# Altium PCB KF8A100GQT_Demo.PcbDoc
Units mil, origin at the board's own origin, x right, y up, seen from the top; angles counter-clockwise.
Board outline 2167.2 x 3149.88 mil, 2 copper layers (Top Layer, Bottom Layer); 44 components, 80 nets, 251 pads, 32 vias.
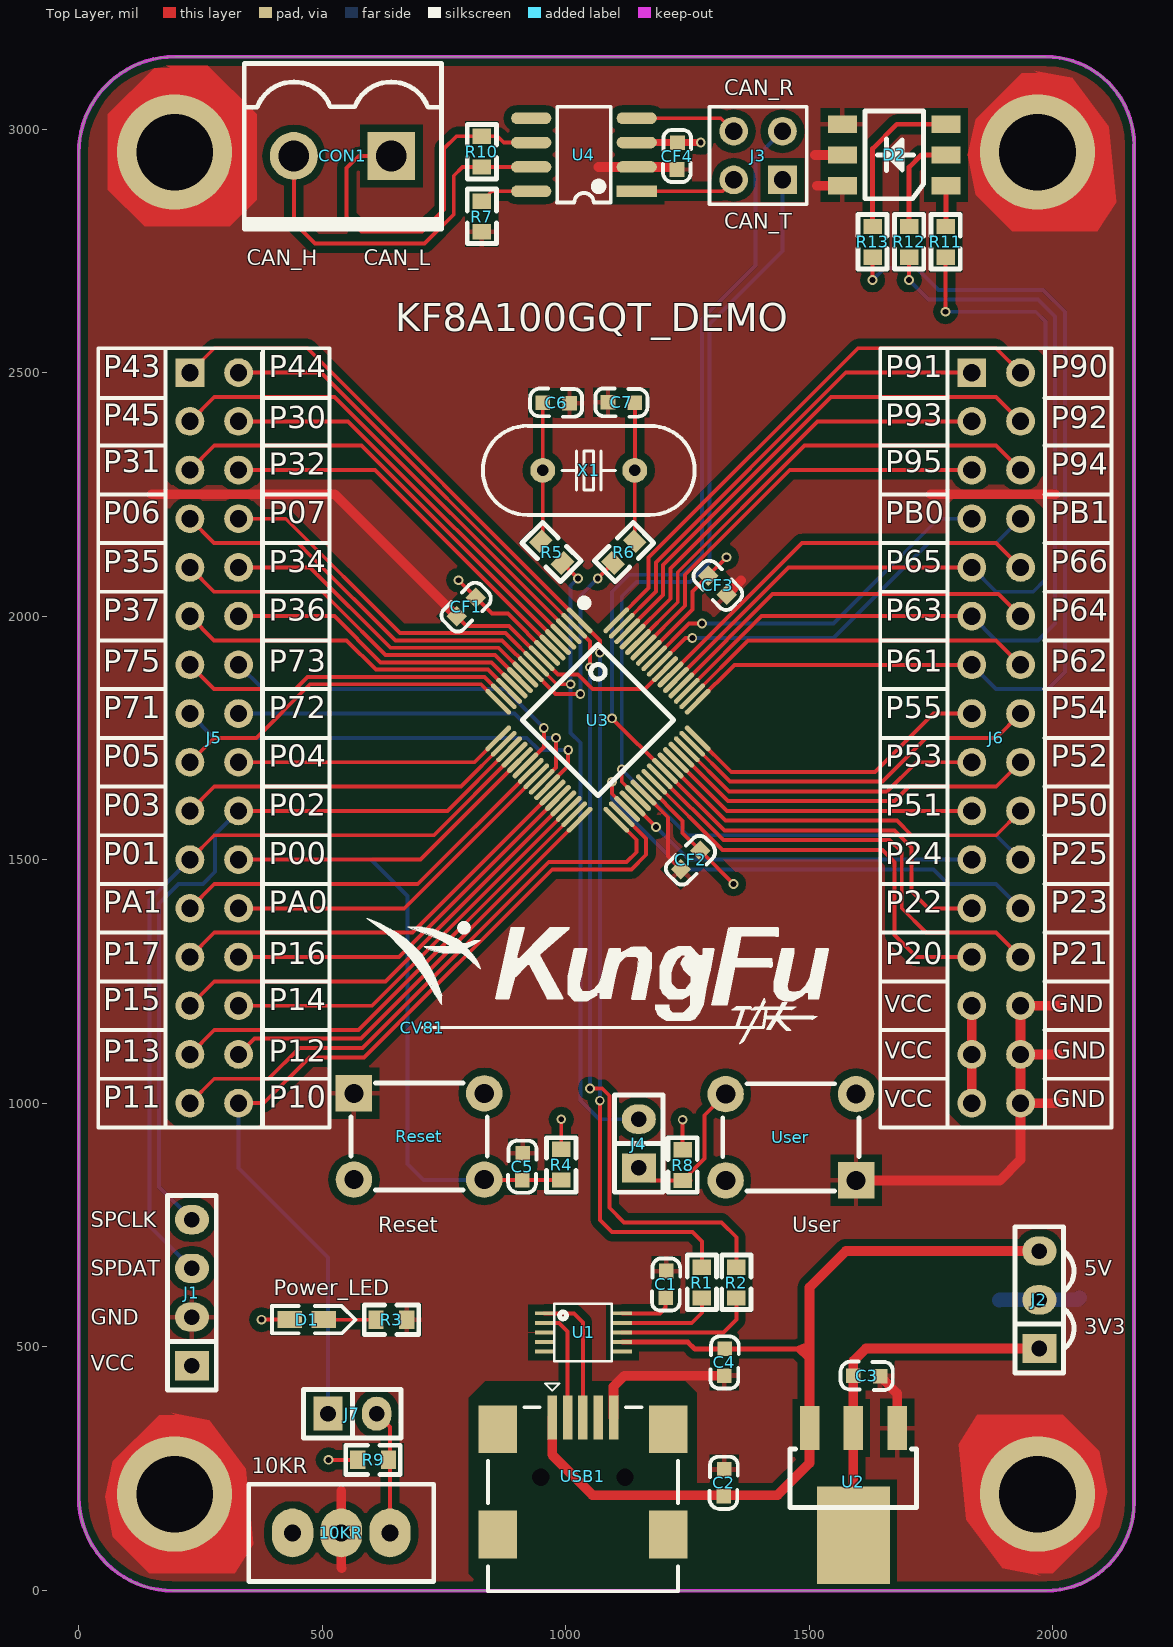
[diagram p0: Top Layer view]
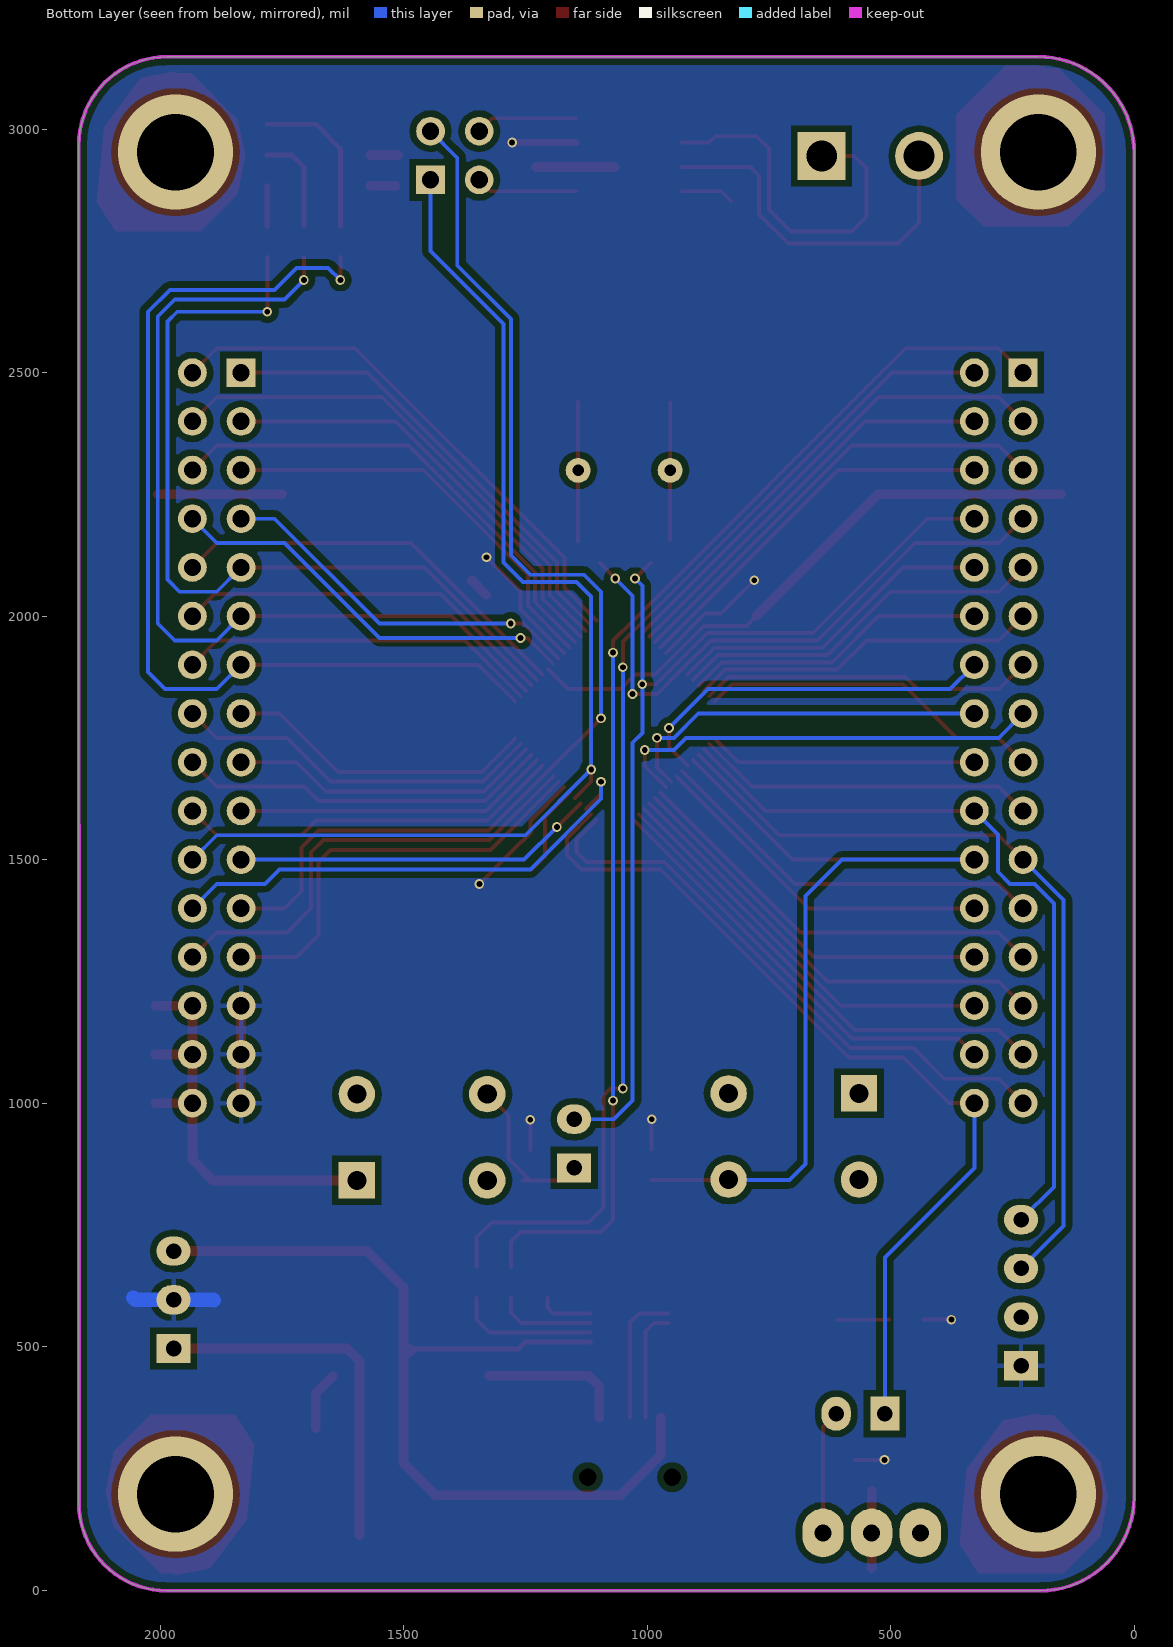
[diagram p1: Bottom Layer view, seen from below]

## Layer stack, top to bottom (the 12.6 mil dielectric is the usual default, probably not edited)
Top Layer: signal copper 1.4
Dielectric: dielectric 12.6, FR-4, Dk 4.8
Bottom Layer: signal copper 1.4

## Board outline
193.16,-1.33 cw(c193.16,191.83) 0,190 0,2951.69 cw(c196.85,2951.69) 196.85,3148.54 1985.93,3148.54 cw(c1985.93,2967.27) 2167.2,2967.27 2167.14,2967.27 2166.9,179.02 2166.97,179.02 cw(c1986.61,179.02) 1986.61,-1.33

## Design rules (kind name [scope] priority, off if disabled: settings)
Clearance [All] p1: gap=5
HoleSize [All] p1: absolutevalues=TRUE maxlimit=157.48 minlimit=1 maxpercent=80.000 minpercent=20.000
PolygonConnect [All vs IsVia] p1: connectstyle=Direct reliefconductorwidth=10 reliefentries=4 polygonreliefangle="90 Angle"
RoutingVias [All] p1: holewidth=28 width=50 viastyle="Through Hole" minholewidth=12 minwidth=20 maxholewidth=157.48 maxwidth=236.22
SolderMaskExpansion [All] p1: expansion=4
TestPointUsage [All] p1: valid=0 allowmultiple=FALSE
Testpoint [All] p1: side=15 testpointundercomponent=TRUE minsize=40 maxsize=100 preferedsize=60 minholesize=0 maxholesize=40 preferedholesize=32 testpointgrid=1 style=1023 order=0-112345678
Width [All] p1: maxlimit=30 minlimit=8 preferedwidth=10
18 further rules are at their usual default settings.

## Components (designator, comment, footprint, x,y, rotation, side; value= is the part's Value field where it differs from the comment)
10KR "10K" 3296W 539.02,117.4 r0 top (schematic designator VR1)
C1 "0.1uF" 0603C 1204.72,599.92 r90 top
C2 "22uF" 0603C 1325.55,248.03 r270 top
C3 "10uF" 0603C 1645.67,438.82 r180 top
C4 "10nF" 0603C 1325,440 r90 top
C5 "100nF" 0603C 912.01,897.05 r270 top
C6 "22pF" 0603C 1007.87,2437.01 r180 top
C7 "22pF" 0603C 1086.61,2439.72 r0 top
CF1 "100nF" 0603C 775.59,2000 r45 top
CF2 "100nF" 0603C 1236.22,1480.32 r45 top
CF3 "100nF" 0603C 1330.71,2043.31 r135 top
CF4 "100nF" 0603C 1229.78,2972.32 r270 top
CON1 "Connector-2P" KF2EDG-5.08-2P 641.73,2944.88 r180 top
CV81 "Comment" LOGO 705,1155 r0 top
D1 "LED" LED-0603B 433.07,555.12 r0 top
D2 "LED-5050" LED-5050W 1779.53,2881.89 r180 top
J1 "DEBUG" "Pin HDR1X4/2.54mm-S" 232.28,460.63 r180 top
J2 "Pin HDR1X3" "Pin HDR1X3/2.54mm-S" 1972.44,496.06 r180 top
J3 "Pin HDR2X2" "Pin HDR2X2/2.54mm-S" 1444.88,2895.75 r90 top
J4 "Pin HDR1X2" "Pin HDR1X2/2.54mm-S" 1150,866.93 r180 top
J5 "Pin HDR2X16" "Pin HDR2X16/2.54mm-S" 228.19,2499.92 r270 top locked
J6 "Pin HDR2X16" "Pin HDR2X16/2.54mm-S" 1833.86,2499.92 r270 top locked
J7 "Pin HDR1X2" "Pin HDR1X2/2.54mm-S" 511.81,362.2 r90 top
R1 "300R" 0603R 1279.53,662.91 r270 top
R2 "300R" 0603R 1350.39,662.91 r270 top
R3 "470R" 0603R 673.23,555.12 r180 top
R4 "10K" 0603R 990.75,841.93 r90 top
R5 "0R" 0603R 948.82,2153.54 r315 top
R6 "0R" 0603R 1141.73,2153.54 r225 top
R7 "NC" 0603R 827.64,2851.97 r270 top
R8 "10K" 0603R 1240,903.93 r270 top
R9 "10K" 0603R 573.19,267.4 r0 top
R10 "120R" 0603R 827.64,2922.32 r90 top
R11 "300R" 0603R 1780,2800 r270 top
R12 "300R" 0603R 1705,2800 r270 top
R13 "300R" 0603R 1630,2800 r270 top
Reset "KEY" DIP-6X6X4.3 565,1020 r0 top (schematic designator K1)
U1 "CH340E" MSOP10 956.54,528.98 r0 top
U2 "AMS1117" SOT223 1590.55,332.52 r180 top
U3 "KF8A100GQT" "LQFP64 7x7" 1059.06,1779.53 r315 top locked
U4 "SN65HVD232D" SOP8 1145.67,2872.32 r180 top
USB1 "MINI-USB" USB-MINI-A 972.28,354.25 r0 top
User "KEY" DIP-6X6X4.3 1596.1,841.22 r180 top (schematic designator K2)
X1 "16M" "OSC HC-49S" 1047.24,2299.21 r180 top

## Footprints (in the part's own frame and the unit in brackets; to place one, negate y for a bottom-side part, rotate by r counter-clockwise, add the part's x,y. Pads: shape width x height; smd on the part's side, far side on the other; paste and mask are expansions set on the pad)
0603C [mil]
  rect 30x30 smd: 1(0.21,-0.35) 2(55.21,-1.35)
  silkscreen extent -26,-30 81,28, body extent -1,-15 62,17, height 12
0603R [mm]
  rect 0.8x0.965 smd: 1(0,0) 2(1.6,0)
  silkscreen extent -0.64,-0.76 2.21,0.76, body extent -0.04,-0.41 1.56,0.41, height 0.45
3296W [mil]
  oval 85x100 hole 35: 1(-100,0) 2(0,0) 3(100,0)
  silkscreen extent -190,-100 190,100, body extent -188,-94 188,94, height 455
DIP-6X6X4.3 [mm]
  rect 1.9x1.9 hole 1: 1(0,0)
  round 1.9 hole 1: 2(0,-4.5) 3(6.8,-4.5) 4(6.8,0)
  silkscreen extent -0.16,-5.04 6.96,0.54, body extent -0.66,-5.25 7.55,0.75, height 4.25
KF2EDG-5.08-2P [mm]
  rect 2.5x2.5 hole 1.6: 1(0,0)
  round 2.5 hole 1.6: 2(5.08,0)
  silkscreen extent -2.62,-4.83 7.67,3.81, body extent -2.54,-4.76 7.62,3.74, height 11.25
LED-0603B [mil]
  rect 50x35 smd: A(0,0.26) K(70,0.26)
  silkscreen extent -36,-28 135,28, body extent 4,-15 66,17, height 24
LED-5050W [mil]
  rect 59.06x35.43 smd: 1(-1.5,-2) 2(211.5,-2) 3(-1.5,-65) 4(211.5,-65) 5(-1.5,-128) 6(211.5,-128)
  silkscreen extent 45,-155 165,25, body extent -1,-162 211,35, height 65
LOGO [mil]
  silkscreen extent -114,-33 835,225
"LQFP64 7x7" [mm]
  oval 1.8x0.26 smd: 1(-4.352,3.254) 2(-4.352,2.854) 3(-4.352,2.454) 4(-4.352,2.054) 5(-4.352,1.654) 6(-4.352,1.254) 7(-4.352,0.854) 8(-4.352,0.454) 9(-4.352,0.054) 10(-4.352,-0.346) 11(-4.352,-0.746) 12(-4.352,-1.146) 13(-4.352,-1.546) 14(-4.352,-1.946) 15(-4.352,-2.346) 16(-4.352,-2.746) 33(4.352,-2.746) 34(4.352,-2.346) 35(4.352,-1.946) 36(4.352,-1.546) 37(4.352,-1.146) 38(4.352,-0.746) 39(4.352,-0.346) 40(4.352,0.054) 41(4.352,0.454) 42(4.352,0.854) 43(4.352,1.254) 44(4.352,1.654) 45(4.352,2.054) 46(4.352,2.454) 47(4.352,2.854) 48(4.352,3.254)
  oval 0.26x1.8 smd: 17(-3,-4.098) 18(-2.6,-4.098) 19(-2.2,-4.098) 20(-1.8,-4.098) 21(-1.4,-4.098) 22(-1,-4.098) 23(-0.6,-4.098) 24(-0.2,-4.098) 25(0.2,-4.098) 26(0.6,-4.098) 27(1,-4.098) 28(1.4,-4.098) 29(1.8,-4.098) 30(2.2,-4.098) 31(2.6,-4.098) 32(3,-4.098) 49(3,4.606) 50(2.6,4.606) 51(2.2,4.606) 52(1.8,4.606) 53(1.4,4.606) 54(1,4.606) 55(0.6,4.606) 56(0.2,4.606) 57(-0.2,4.606) 58(-0.6,4.606) 59(-1,4.606) 60(-1.4,4.606) 61(-1.8,4.606) 62(-2.2,4.606) 63(-2.6,4.606) 64(-3,4.606)
  silkscreen extent -4.95,-2.54 2.79,4.19
MSOP10 [mm]
  rect 1x0.2 smd: 1(0,1) 2(0,0.5) 3(0,0) 4(0,-0.5) 5(0,-1) 6(4.064,-1) 7(4.064,-0.5) 8(4.064,0) 9(4.064,0.5) 10(4.064,1)
  silkscreen extent 0.51,-1.5 3.51,1.5
"OSC HC-49S" [mm]
  round 1.3 hole 0.6: 1(-2.4,0) 2(2.4,0)
  silkscreen extent -5.52,-2.32 5.52,2.33, body extent -5.53,-2.29 5.53,2.36, height 4.13
"Pin HDR1X2/2.54mm-S" [mil]
  rect 70x60 hole 32: 1(0,0)
  oval 70x60 hole 32: 2(0,-100)
  silkscreen extent -50,-150 50,50, body extent -50,-150 50,50, height 336
"Pin HDR1X3/2.54mm-S" [mil]
  rect 70x60 hole 32: 1(0,0)
  oval 70x60 hole 32: 2(0,-100) 3(0,-200)
  silkscreen extent -50,-250 50,50, body extent -50,-250 50,50, height 336
"Pin HDR1X4/2.54mm-S" [mil]
  rect 70x60 hole 32: 1(0,0)
  oval 70x60 hole 32: 2(0,-100) 3(0,-200) 4(0,-300)
  silkscreen extent -50,-350 50,50, body extent -50,-350 50,50, height 336
"Pin HDR2X2/2.54mm-S" [mm] "Connector; Header; 2x2 Position"
  rect 1.5x1.5 hole 0.9: 1(0,0)
  round 1.5 hole 0.9: 2(0,2.54) 3(2.54,0) 4(2.54,2.54)
  silkscreen extent -1.27,-1.27 3.81,3.81, body extent -1.27,-1.27 3.81,3.81, height 7.58
"Pin HDR2X16/2.54mm-S" [mm] "Connector; Header; 16x2 Position"
  rect 1.5x1.5 hole 0.9: 1(0,0)
  round 1.5 hole 0.9: 2(0,2.54) 3(2.54,0) 4(2.54,2.54) 5(5.08,0) 6(5.08,2.54) 7(7.62,0) 8(7.62,2.54) 9(10.16,0) 10(10.16,2.54) 11(12.7,0) 12(12.7,2.54) 13(15.24,0) 14(15.24,2.54) 15(17.78,0) 16(17.78,2.54) 17(20.32,0) 18(20.32,2.54) 19(22.86,0) 20(22.86,2.54) 21(25.4,0) 22(25.4,2.54) 23(27.94,0) 24(27.94,2.54) 25(30.48,0) 26(30.48,2.54) 27(33.02,0) 28(33.02,2.54) 29(35.56,0) 30(35.56,2.54) 31(38.1,0) 32(38.1,2.54)
  silkscreen extent -1.27,-1.27 39.37,3.81, body extent -1.27,-1.27 39.37,3.81, height 7.58
SOP8 [mm]
  rect 2.1x0.6 smd: 1(0,0)
  oval 2.1x0.6 smd: 2(0,-1.27) 3(0,-2.54) 4(0,-3.81) 5(5.5,-3.81) 6(5.5,-2.54) 7(5.5,-1.27) 8(5.5,0)
  silkscreen extent 1.35,-4.41 4.15,0.6, body extent -0.36,-4.37 5.64,0.63, height 1.9
SOT223 [mil]
  rect 40x90 smd: 1(-90,0) 2(0,0) 3(90,0)
  rect 150x200 smd: 2(0,220)
  silkscreen extent -130,43 130,163, body extent -130,-30 126,246, height 65
USB-MINI-A [mm]
  rect 2x2.5 smd: 0(-2.85,-6.108) 0(-2.85,-0.608) 0(6.05,-6.108) 0(6.05,-0.608)
  rect 0.5x2.3 smd: 1(0,0) 2(0.8,0) 3(1.6,0) 4(2.4,0) 5(3.2,0)
  round 0.6 hole 0.9 unplated: MH1(3.8,-3.108) MH2(-0.6,-3.108)
  silkscreen extent -3.35,-9.06 6.55,1.78, body extent -3.17,-9.04 6.33,0.66, height 3.95

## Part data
10KR: library part RESVR
C1 C2 C3 C4 C5 C6 C7 CF1 CF2 CF3 CF4: library part CAP, "无极性电容"
J1: library part "Pin HDR1X4"
R1 R2 R3 R4 R5 R6 R7 R8 R9 R10 R11 R12 R13: library part RES
U1: "USB to TTL Serial / UART"
U2: "三端稳压芯片"
U3: "QPF64"
U4: library part TJA1050
X1: library part XTAL-2P, "2脚无源脚晶振"

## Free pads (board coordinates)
  round 236.22 hole 157.48: 0(196.85,196.85) 0(196.85,2952.76) 0(1968.5,196.85) 0(1968.5,2952.76)

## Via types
v1: diameter 20, hole 12, Top Layer to Bottom Layer, 28 vias
v2: diameter 236.22, hole 157.48, Top Layer to Bottom Layer, 4 vias

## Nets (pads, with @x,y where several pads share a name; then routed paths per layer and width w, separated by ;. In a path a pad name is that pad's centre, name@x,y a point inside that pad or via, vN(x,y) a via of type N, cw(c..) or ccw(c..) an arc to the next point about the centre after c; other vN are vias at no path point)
ADC: J5.32 J7.1 U3.34 | length 1865.7
  Top Layer w8: J5.32 379.92,999.92 473.85,1093.85 586.06,1093.85 972.2,1480 1135,1480 1165,1510 1165,1542.96 U3.34
  Bottom Layer w8: J5.32 328.19,866.81 511.81,683.19 J7.1
CAN_H: CON1.2 R10.1 U4.7 | length 753.5
  Top Layer w8: CON1.2 441.73,2808.27 485,2765 710,2765 770,2825 770,2904.25 788.07,2922.32 R10.1 U4.7
CAN_L: CON1.1 R10.2 U4.6 | length 753.1
  Top Layer w8: CON1.1 574.88,2944.88 550,2920 550,2820 580,2790 705,2790 750,2835 750,2960 775.31,2985.31 R10.2 859.69,2985.31 872.68,2972.32 U4.6
CAN_RX: J3.4 U4.4 | length 210.2
  Top Layer w8: U4.4 1318.31,3022.32 J3.4
CAN_TX: J3.2 U4.1 | length 208.9
  Top Layer w8: U4.1 1321.46,2872.32 J3.2
GND: 10KR.2 C1.2 C2.1 C3.1 C4.1 C5.1 C6.1 C7.1 CF1.1 CF2.1 CF3.1 CF4.2 D2.2 D2.4 D2.6 J1.2 J6.28 J6.30 J6.32 pad.0 R3.1 R7.2 Reset.1 U1.3 U2.1 U3.8 U3.38 U3.55 U4.2 USB1.5 User.1 | length 3471.2
  Top Layer w8: CF1.1 795.89,1980 883.86,1980 U3.8 983.86,1880 1025,1880 1055,1850 1162.93,1850 U3.55 ; U3.38 1210,1587.05 1210,1506.84 CF2.1
  Top Layer w20: 150,2250 525.89,2250 CF1.1 ; 539.02,204.02 10KR.2 539.02,45.98 540,45 ; 1067.32,2922.32 U4.2 CF4.2@1228.08,2922.32 ; USB1.5 1098.27,418.27 1120,440 ; 1120.35,440.21 C4.1 ; CF3.1 1360,2072.9 ; 1511.89,2946.89 D2.4 ; 1516.11,2883.89 D2.2 ; User.1 1891.22,841.22 1933.86,883.86 J6.32 ; C3.1 1680.55,404.08 U2.1 ; 1750,2250 2005,2250 ; 2009.92,999.92 J6.32 ; 2009.92,1099.92 J6.30 ; 2009.92,1199.92 J6.28 J6.30 ; J6.32 J6.30
  other v2: 196.85,196.85 1968.5,196.85 196.85,2952.76 1968.5,2952.76
INT1: J4.2 J5.8 R5.2 U3.9 | length 2090
  Top Layer w8: J5.8 425.08,2199.92 660,1965 876.59,1965 U3.9 981.59,1860 v1(1010,1860) ; R5.2 v1(1025,2077.36)
  Bottom Layer w8: v1(1025,2077.36) 1010,2062.36 v1(1010,1860) 1010,1760 1030,1740 1030,1005 1068.07,966.93 J4.2
MCU_RX: J5.2 R2.1 U3.2 | length 2491.4
  Top Layer w8: J5.2 497.57,2499.92 U3.2 1050,1947.49 v1(1050,1895) ; v1(1050,1030) 1075,1030 1090,1015 1090,785 1120,755 1320,755 1350.39,724.61 R2.1
  Bottom Layer w8: v1(1050,1030) v1(1050,1895)
MCU_TX: J5.1 R1.1 U3.1 | length 2581.5
  Top Layer w8: J5.1 278.27,2550 469.76,2550 U3.1 1070,1949.76 v1(1070,1925) ; v1(1070,1005) 1070,810 1070,760 1095,735 1260,735 1279.53,715.47 R1.1
  Bottom Layer w8: v1(1070,1005) v1(1070,1925)
NetC1_1: C1.1 U1.10 | length 113.5
  Top Layer w8: U1.10 1193.35,568.35 1205.08,580.08 C1.1
NetC6_2: C6.2 R5.1 X1.2 | length 286.5
  Top Layer w8: X1.2@948.82,2295.28 X1.2 ; C6.2 952.66,2299.31 X1.2 ; R5.1@952.76,2157.48 X1.2
NetC7_2: C7.2 R6.1 X1.1 | length 286.1
  Top Layer w8: R6.1 X1.1 1141.83,2299.31 C7.2@1141.83,2439.59
NetD1_K: D1.K R3.2 | length 107.3
  Top Layer w8: D1.K 503.33,555.12 R3.2
NetD2_1: D2.1 R11.1 | length 84.3
  Top Layer w10: R11.1 1781.03,2801.03 D2.1
NetD2_3: D2.3 R12.1 | length 208.3
  Top Layer w10: R12.1 1705,2921.89 1730,2946.89 D2.3
NetD2_5: D2.5 R13.1 | length 331.7
  Top Layer w10: R13.1 1630,2960 1679.89,3009.89 D2.5
NetJ4_1: J4.1 R8.2 User.3 | length 344.9
  Top Layer w8: J4.1 1175.71,841.22 R8.2@1240,841.22 ; R8.2@1226.02,841.22 R8.2@1240,841.22 ; R8.2 R8.2@1240.28,841.22 ; R8.2@1256.22,841.22 R8.2@1240.28,841.22 ; User.3 1285,975 1285,885.94 R8.2@1240.28,841.22 ; R8.2@1240,841.22 R8.2@1240.28,841.22
NetJ7_2: 10KR.3 J7.2 R9.2 | length 256.1
  Top Layer w8: J7.2 639.02,335 10KR.3
NetR1_2: R1.2 U1.9 | length 202
  Top Layer w8: U1.9 1258.66,548.66 1279.53,569.53 R1.2
NetR2_2: R2.2 U1.8 | length 289.3
  Top Layer w8: U1.8 1323.98,528.98 1350.39,555.39 R2.2
NetR7_1: R7.1 U4.8 | length 109.9
  Top Layer w8: R7.1 847.99,2872.32 U4.8
NRST: C5.2 J5.22 R4.1 Reset.3 U3.21 | length 1919.8
  Top Layer w8: J5.22 701.5,1499.92 U3.21 ; Reset.3@813.58,841.93 R4.1
  Bottom Layer w8: J5.22 600.08,1499.92 675,1425 675,875 708.07,841.93 Reset.3@813.58,841.93
P01: J1.3 J5.21 U3.20 | length 1665.9
  Top Layer w8: J5.21 278.27,1550 729.31,1550 U3.20
  Bottom Layer w8: J5.21 145,1416.73 145,747.91 J1.3
P02: J1.4 J5.20 U3.19 | length 1572.1
  Top Layer w8: J5.20 756.96,1599.92 U3.19
  Bottom Layer w8: J1.4 165,827.91 165,1410 205,1450 255,1450 280,1475 280,1551.73 J5.20
P03: J5.19 U3.18 | length 701.5
  Top Layer w8: J5.19 278.27,1650 784.77,1650 U3.18
P04: J5.18 U3.17 | length 553.6
  Top Layer w8: J5.18 812.42,1699.92 U3.17
P05: J5.17 U3.16 | length 714.4
  Top Layer w8: J5.17 278.27,1750 365,1750 475,1860 825.69,1860 U3.16
P06: J5.7 R6.2 U3.10 | length 1247.7
  Top Layer w8: J5.7 278.11,2150 450,2150 476.15,2123.85 650,1950 869.32,1950 U3.10 979.32,1840 v1(1030,1840) ; v1(1065.55,2077.36) R6.2
  Bottom Layer w8: v1(1030,1840) 1030,2041.81 v1(1065.55,2077.36)
P6C1: J6.9 R11.2 U3.53 | length 1740.8
  Top Layer w8: U3.53 1457.4,2099.92 J6.9 ; v1(1780,2625) R11.2
  Bottom Layer w8: v1(1780,2625) 1965,2625 1985,2605 1985,2075 1960,2050 1883.78,2050 J6.9
P6C2: J6.11 R12.2 U3.51 | length 1863.3
  Top Layer w8: U3.51 1401.94,1999.92 J6.11 ; v1(1705,2690) R12.2
  Bottom Layer w8: v1(1705,2690) 1745,2650 1790,2650 1970,2650 2005,2615 2005,1985 1970,1950 1883.78,1950 J6.11
P6C3: J6.13 R13.2 U3.49 | length 2050.4
  Top Layer w8: U3.49 1346.48,1899.92 J6.13 ; v1(1630,2690) R13.2
  Bottom Layer w8: v1(1630,2690) 1655,2715 1720,2715 1765,2670 1980,2670 2025,2625 2025,1885 1990,1850 1883.78,1850 J6.13
P11: J5.31 U3.33 | length 1214.2
  Top Layer w8: J5.31 278.27,1050 390,1050 452.92,1112.92 582.92,1112.92 965,1495 1125,1495 1145,1515 1145,1540.69 U3.33
P12: J5.30 U3.32 | length 899.9
  Top Layer w8: J5.30 361.19,1132.93 579.49,1132.93 U3.32
P13: J5.29 U3.31 | length 993.4
  Top Layer w8: J5.29 278.27,1150 574.29,1150 U3.31
P14: J5.28 U3.30 | length 845.5
  Top Layer w8: J5.28 601.94,1199.92 U3.30
P15: J5.27 U3.29 | length 938.9
  Top Layer w8: J5.27 278.27,1250 629.75,1250 U3.29
P16: J5.26 U3.28 | length 791
  Top Layer w8: J5.26 657.4,1299.92 U3.28
P17: J5.25 U3.27 | length 884.5
  Top Layer w8: J5.25 278.27,1350 685.21,1350 U3.27
P20: J6.25 U3.40 | length 889.1
  Top Layer w8: U3.40 1321.59,1520 1650,1520 1675,1495 1675,1345 1720.08,1299.92 J6.25
P21: J6.26 U3.41 | length 962.1
  Top Layer w8: U3.41 1323.86,1540 1665,1540 1690,1515 1690,1400 1740,1350 1883.78,1350 J6.26
P22: J3.3 J6.23 U3.42 | length 2367.9
  Top Layer w8: v1(1095,1790) U3.42 1326.13,1560 1675,1560 1710,1525 1710,1435 1745.08,1399.92 J6.23
  Bottom Layer w8: v1(1095,1790) 1095,2050 1130,2085 1240,2085 1280,2125 1280,2610 1390,2720 1390,2940.87 J3.3
P23: J6.24 U3.35 | length 1035.8
  Top Layer w8: v1(1095,1660) 1095,1635.23 U3.35
  Bottom Layer w8: v1(1095,1660) 1095,1625 1240,1480 1755,1480 1785,1450 1883.78,1450 J6.24
P24: J6.21 U3.36 | length 744.5
  Top Layer w8: U3.36 v1(1185.5,1567.01)
  Bottom Layer w8: v1(1185.5,1567.01) 1252.58,1499.92 J6.21
P25: J3.1 J6.22 U3.37 | length 2379.7
  Top Layer w8: v1(1115,1685) 1115,1659.78 U3.37
  Bottom Layer w8: J3.1 1444.88,2749.88 1295,2600 1295,2110 1255,2070 1145,2070 1115,2040 v1(1115,1685) 1250,1550 1883.78,1550 J6.22
P30: J5.4 U3.4 | length 850
  Top Layer w8: J5.4 553.02,2399.92 U3.4
P31: J5.5 U3.5 | length 943.5
  Top Layer w8: J5.5 278.27,2350 580.67,2350 U3.5
P32: J5.6 U3.6 | length 795.5
  Top Layer w8: J5.6 608.48,2299.92 U3.6
P34: J5.10 U3.11 | length 680.1
  Top Layer w8: J5.10 475.08,2099.92 640,1935 862.05,1935 U3.11
P35: J5.9 U3.12 | length 773.5
  Top Layer w8: J5.9 278.11,2050 500,2050 530.86,2019.14 630,1920 854.78,1920 U3.12
P36: J5.12 U3.13 | length 625.6
  Top Layer w8: J5.12 525.08,1999.92 620,1905 847.51,1905 U3.13
P37: J5.11 U3.14 | length 719.1
  Top Layer w8: J5.11 278.11,1950 550,1950 610,1890 840.23,1890 U3.14
P45: J5.3 U3.3 | length 998
  Top Layer w8: J5.3 278.27,2450 525.22,2450 U3.3
P50: J6.20 U3.43 | length 798.8
  Top Layer w8: U3.43 1328.4,1580 1680,1580 1710,1550 1883.94,1550 J6.20
P51: J6.19 U3.44 | length 650.9
  Top Layer w8: U3.44 1330.75,1599.92 J6.19
P52: J6.18 U3.45 | length 769.1
  Top Layer w8: U3.45 1332.94,1620 1675,1620 1705,1650 1883.94,1650 J6.18
P53: J6.17 U3.46 | length 646
  Top Layer w8: U3.46 1335.22,1640 1660,1640 1719.92,1699.92 J6.17
P54: J6.16 U3.47 | length 764.4
  Top Layer w8: U3.47 1337.49,1660 1650,1660 1740,1750 1883.94,1750 J6.16
P55: J6.15 U3.48 | length 641.3
  Top Layer w8: U3.48 1339.76,1680 1635,1680 1754.92,1799.92 J6.15
P62: J6.14 U3.50 | length 742.4
  Top Layer w8: U3.50 1374.29,1950 1883.78,1950 J6.14
P64: J6.12 U3.52 | length 792.7
  Top Layer w8: U3.52 1424.75,2045 1888.78,2045 J6.12
P66: J6.10 U3.54 | length 851.3
  Top Layer w8: U3.54 1485.21,2150 1883.78,2150 J6.10
P71: J5.15 U3.26 | length 902.1
  Top Layer w8: U3.26 1005,1692.07 v1(1005,1725)
  Bottom Layer w8: J5.15 278.11,1750 920,1750 945,1725 v1(1005,1725)
P72: J5.16 U3.25 | length 774.8
  Top Layer w8: U3.25 980,1689.34 v1(980,1750)
  Bottom Layer w8: J5.16 895.08,1799.92 945,1750 v1(980,1750)
P73: J5.14 U3.22 | length 773
  Top Layer w8: U3.22 955,1731.15 v1(955,1770)
  Bottom Layer w8: J5.14 378.11,1850 875,1850 v1(955,1770)
P75: J5.13 U3.15 | length 691.8
  Top Layer w8: J5.13 278.11,1850 445,1850 470,1875 832.96,1875 U3.15
P90: J6.2 U3.64 | length 1118.9
  Top Layer w8: U3.64 1170,2057.51 1170,2120 1600,2550 1883.78,2550 J6.2
P91: J6.1 U3.63 | length 969.3
  Top Layer w8: U3.63 1185,2050.23 1185,2110 1574.92,2499.92 J6.1
P92: J6.4 U3.62 | length 1064.1
  Top Layer w8: U3.62 1200,2042.96 1200,2105 1545,2450 1883.78,2450 J6.4
P93: J6.3 U3.61 | length 916.2
  Top Layer w8: U3.61 1215,2035.69 1215,2097.8 1517.13,2399.92 J6.3
P94: J6.6 U3.60 | length 1009.4
  Top Layer w8: U3.60 1230,2028.42 1230,2090 1490,2350 1883.78,2350 J6.6
P95: J6.5 U3.59 | length 862.7
  Top Layer w8: U3.59 1245,2021.15 1245,2085 1459.92,2299.92 J6.5
PA0: J5.24 U3.24 | length 723.5
  Top Layer w8: J5.24 668.31,1399.92 U3.24
PA1: J5.23 U3.23 | length 817
  Top Layer w8: J5.23 278.27,1450 696.12,1450 U3.23
PB0: J6.7 U3.57 | length 770.8
  Top Layer w8: U3.57 1253.39,1985 v1(1280,1985)
  Bottom Layer w8: v1(1280,1985) 1550,1985 1764.92,2199.92 J6.7
PB1: J6.8 U3.56 | length 864.3
  Top Layer w8: U3.56 1245.66,1955 v1(1260,1955)
  Bottom Layer w8: v1(1260,1955) 1550,1955 1745,2150 1883.94,2150 J6.8
USB_3.3V: C3.2 J2.1 U2.2 | length 750.5
  Top Layer w20: U2.2@1590.55,112.52 1590.55,332.52 1590.55,470.55 1616.06,496.06 J2.1
USB_5V: C2.2 C4.2 J2.3 U1.7 U2.3 USB1.1 | length 1929.2
  Top Layer w8: 1499.9,484.35 1500.55,485
  Top Layer w10: U1.7 1250.71,509.29 1265,495 1475.55,495 1495.55,475 1500.55,475
  Top Layer w20: USB1.1 972.28,277.72 1055,195 1435,195 1500.55,260.55 U2.3 1500.55,475 1500.55,485 1500.55,621.61 1575,696.06 J2.3
USB_D+: U1.1 USB1.3 | length 281.9
  Top Layer w8: U1.1 1016.65,568.35 1035.27,549.73 USB1.3
USB_D-: U1.2 USB1.2 | length 231.4
  Top Layer w8: U1.2 986.34,548.66 1003.78,531.22 USB1.2
VCC: CF1.2 CF2.2 CF3.2 CF4.1 D1.A J1.1 J2.2 J6.27 J6.29 J6.31 R4.2 R8.1 R9.1 U3.7 U3.39 U3.58 U4.3 | length 1517.2
  Top Layer w8: v1(375.37,555.37) D1.A ; v1(512.6,267.4) R9.1 ; v1(780,2073.67) CF1.2 848.67,2005 881.13,2005 U3.7 ; R4.2 v1(990.75,966.73) ; U3.39 1240,1579.32 1240,1554.62 CF2.2 v1(1344.62,1450) ; U3.58 1260,2013.88 1260,2050.68 CF3.2 v1(1330,2120.68) ; R8.1 v1(1240,965.74)
  Top Layer w15: U4.3 v1(1277.32,2972.32)
  Top Layer w20: J6.31 J6.29 J6.27
  Bottom Layer w30: 1890,595 1891.06,596.06 J2.2 2051.06,596.06 2055,600
pads on no net: 10KR.1 Reset.2 Reset.4 U1.4 U1.5 U1.6 U4.5 USB1.0 USB1.4 USB1.MH1 USB1.MH2 User.2 User.4

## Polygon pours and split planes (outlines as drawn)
GND on Top Layer "Top Layer-No Net" (solid, remove dead copper, pour order 1000): -10,3195 -10,55 165,-120 2195,-120 2310,-5 2310,3120 2215,3215 10,3215 -10,3195
VCC on Bottom Layer "Top Layer-No Net" (solid, remove dead copper, pour order 1001): -5,3195 -5,55 170,-120 2200,-120 2315,-5 2315,3120 2220,3215 15,3215 -5,3195

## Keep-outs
Keep-Out Layer:
  lines w7.87: 2166.9,179.02 2167.14,2967.27 ; 2166.97,179.02 cw(c1986.61,179.02) 1986.61,-1.33 193.16,-1.33 cw(c193.16,191.83) 0,190 0,2951.69 cw(c196.85,2951.69) 196.85,3148.54 1985.93,3148.54 cw(c1985.93,2967.27) 2167.2,2967.27

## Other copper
Top Layer:
  region net GND: 200,359.09 165,359.09 70,264.09 53.9,191.85 70,109.09 145,34.09 320,34.09 358.35,94.09 343.35,249.09 268.35,349.09 190,364.09
  region net GND: 1965.35,34.61 2000.35,34.61 2095.35,129.61 2111.45,201.85 2095.35,284.61 2020.35,359.61 1845.35,359.61 1807.01,299.61 1822.01,144.61 1897.01,44.61 1975.35,29.61
  region net GND: 1971.65,3115 1936.65,3115 1841.65,3020 1825.56,2947.76 1841.65,2865 1916.65,2790 2091.65,2790 2130,2850 2115,3005 2040,3105 1961.65,3120
  region net GND: 190,3125 155,3125 60,3030 60,2875 135,2800 310,2800 365,2855 365,3030 265,3130 180,3130
  pour cut-out: 2020,696.06 2020,496.06 1616.06,496.06 1590.55,470.55 1590.55,4.22 1585,-1.33 1500.55,83.12 1500.55,621.61 1510.55,621.61 1585,696.06
  pour cut-out: 835,-1.33 1243.67,-1.33 1270,25 1270,405 1245,430 835,430 800,395 800,33.67
  pour cut-out: 1780,2225 1795.38,2240.38 1959.62,2240.38 1980,2220 1980,960 1970,950 1815,950 1785,980 1785,2220
  pour cut-out: 1785,2550 1965,2550 1985,2530 1985,2293.85 1961.46,2270.3 1804.24,2270.3 1804.24,2275.68 1780,2299.92 1785,2304.92
  pour cut-out: 1065,1965 880,1780 1050,1610 1075,1610 1234.26,1769.26 1234.26,1778.58 1245,1789.32 1245,1800 1080,1965
  pour cut-out: 180,2220 191.05,2220 207.25,2236.2 358.8,2236.2 380,2215 380,965 365,950 200,950 180,970
  pour cut-out: 180,2550 180,2280 190,2270 365,2270 380,2285 380,2545 375,2550
  region net USB_5V: 1475.55,495 1475.55,500.55 1485,505 1500.55,510 1500.55,475

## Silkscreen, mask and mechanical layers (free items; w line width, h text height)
Top Overlay:
  lines w7.87: 40,950 515,950 ; 40,951.36 40,2550 515,2550 515,951.36 ; 40,1050 178.19,1050 ; 40,1150 178.19,1150 ; 40,1250 178.19,1250 ; 40,1350 178.19,1350 ; 40,1450 178.19,1450 ; 40,1550 178.19,1550 ; 40,1650 178.19,1650 ; 40,1750 178.19,1750 ; 40,1850 178.19,1850 ; 40,1950 178.19,1950 ; 40,2050 178.19,2050 ; 40,2150 178.19,2150 ; 40,2250 178.19,2250 ; 40,2350 178.19,2350 ; 40,2447.64 178.19,2447.64 ; 376.02,950 376.02,2540 ; 376.81,1050 515,1050 ; 376.81,1150 515,1150 ; 376.81,1250 515,1250 ; 376.81,1350 515,1350 ; 376.81,1450 515,1450 ; 376.81,1550 515,1550 ; 376.81,1650 515,1650 ; 376.81,1750 515,1750 ; 376.81,1850 515,1850 ; 376.81,1950 515,1950 ; 376.81,2050 515,2050 ; 376.81,2150 515,2150 ; 376.81,2250 515,2250 ; 376.81,2350 515,2350 ; 376.81,2447.64 515,2447.64 ; 1645.67,950 2120.67,950 ; 1645.67,951.36 1645.67,2550 2120.67,2550 2120.67,951.36 ; 1645.67,1050 1783.86,1050 ; 1645.67,1150 1783.86,1150 ; 1645.67,1250 1783.86,1250 ; 1645.67,1350 1783.86,1350 ; 1645.67,1450 1783.86,1450 ; 1645.67,1550 1783.86,1550 ; 1645.67,1650 1783.86,1650 ; 1645.67,1750 1783.86,1750 ; 1645.67,1850 1783.86,1850 ; 1645.67,1950 1783.86,1950 ; 1645.67,2050 1783.86,2050 ; 1645.67,2150 1783.86,2150 ; 1645.67,2250 1783.86,2250 ; 1645.67,2350 1783.86,2350 ; 1645.67,2447.64 1783.86,2447.64 ; 1982.48,1050 2120.67,1050 ; 1982.48,1150 2120.67,1150 ; 1982.48,1250 2120.67,1250 ; 1982.48,1350 2120.67,1350 ; 1982.48,1450 2120.67,1450 ; 1982.48,1550 2120.67,1550 ; 1982.48,1650 2120.67,1650 ; 1982.48,1750 2120.67,1750 ; 1982.48,1850 2120.67,1850 ; 1982.48,1950 2120.67,1950 ; 1982.48,2050 2120.67,2050 ; 1982.48,2150 2120.67,2150 ; 1982.48,2250 2120.67,2250 ; 1982.48,2350 2120.67,2350 ; 1982.48,2447.64 2120.67,2447.64
  lines w10: 2022.44,578.07 cw(c1992.42,536.61) 2023.58,495.99 ; 2022.44,696.43 cw(c1992.42,654.97) 2023.58,614.36
  text "CAN_R" at 1325,3070 h31.5
  text "CAN_T" at 1325,2795 h31.5
  text "CAN_H" at 345,2720 h31.5
  text "CAN_L" at 585,2720 h31.5
  text "KF8A100GQT_DEMO" at 650,2565 h98.43
  text "P43" at 50,2475 h78.74
  text "P44" at 390,2475 h78.74
  text "P91" at 1655.67,2475 h78.74
  text "P90" at 1995.67,2475 h78.74
  text "P45" at 50,2375 h78.74
  text "P93" at 1655.67,2375 h78.74
  text "P30" at 390,2370 h78.74
  text "P92" at 1995.67,2370 h78.74
  text "P31" at 50,2280 h78.74
  text "P95" at 1655.67,2280 h78.74
  text "P32" at 390,2275 h78.74
  text "P94" at 1995.67,2275 h78.74
  text "P06" at 50,2175 h78.74
  text "P07" at 390,2175 h78.74
  text "PB0" at 1655.67,2175 h78.74
  text "PB1" at 1995.67,2175 h78.74
  text "P35" at 50,2075 h78.74
  text "P34" at 390,2075 h78.74
  text "P65" at 1655.67,2075 h78.74
  text "P66" at 1995.67,2075 h78.74
  text "P37" at 50,1975 h78.74
  text "P36" at 390,1975 h78.74
  text "P63" at 1655.67,1975 h78.74
  text "P64" at 1995.67,1975 h78.74
  text "P75" at 50,1870 h78.74
  text "P73" at 390,1870 h78.74
  text "P61" at 1655.67,1870 h78.74
  text "P62" at 1995.67,1870 h78.74
  text "P71" at 50,1775 h78.74
  text "P72" at 390,1775 h78.74
  text "P55" at 1655.67,1775 h78.74
  text "P54" at 1995.67,1775 h78.74
  text "P05" at 50,1675 h78.74
  text "P04" at 390,1675 h78.74
  text "P53" at 1655.67,1675 h78.74
  text "P52" at 1995.67,1675 h78.74
  text "P03" at 50,1575 h78.74
  text "P02" at 390,1575 h78.74
  text "P51" at 1655.67,1575 h78.74
  text "P50" at 1995.67,1575 h78.74
  text "P01" at 50,1475 h78.74
  text "P00" at 390,1475 h78.74
  text "P24" at 1655.67,1475 h78.74
  text "P25" at 1995.67,1475 h78.74
  text "PA1" at 50,1375 h78.74
  text "PA0" at 390,1375 h78.74
  text "P22" at 1655.67,1375 h78.74
  text "P23" at 1995.67,1375 h78.74
  text "P17" at 50,1270 h78.74
  text "P16" at 390,1270 h78.74
  text "P20" at 1655.67,1270 h78.74
  text "P21" at 1995.67,1270 h78.74
  text "P15" at 50,1175 h78.74
  text "P14" at 390,1175 h78.74
  text "VCC" at 1655,1175 h59.06
  text "GND" at 1995.67,1175 h59.06
  text "VCC" at 1655,1080 h59.06
  text "GND" at 2000.67,1080 h59.06
  text "P13" at 50,1070 h78.74
  text "P12" at 390,1070 h78.74
  text "VCC" at 1655,980 h59.06
  text "GND" at 2000,980 h59.06
  text "P11" at 50,975 h78.74
  text "P10" at 390,975 h78.74
  text "SPCLK" at 25,745 h31.5
  text "Reset" at 615,735 h31.5
  text "User" at 1465,735 h31.5
  text "SPDAT" at 25,645 h31.5
  text "5V" at 2065,645 h31.5
  text "Power_LED" at 400,605 h31.5
  text "GND" at 25,545 h31.5
  text "3V3" at 2065,525 h31.5
  text "VCC" at 25,450 h31.5
  text "10KR" at 355,240 h31.5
